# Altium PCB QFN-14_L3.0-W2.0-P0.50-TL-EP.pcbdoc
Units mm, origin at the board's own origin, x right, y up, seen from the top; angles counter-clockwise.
Board outline 15.48 x 16.33 mm, 2 copper layers (Top Layer, Bottom Layer), stack 0 mm thick; 1 components, 0 nets, 12 pads, 0 vias.
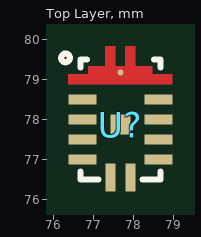
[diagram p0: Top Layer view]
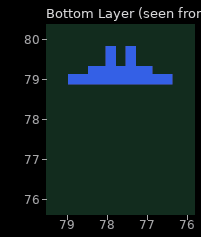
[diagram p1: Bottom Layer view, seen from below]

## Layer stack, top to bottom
Top Layer: signal copper (thickness not stored)
Bottom Layer: signal copper (thickness not stored)

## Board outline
85.333,69.85 69.85,69.85 69.85,86.176 85.333,86.176

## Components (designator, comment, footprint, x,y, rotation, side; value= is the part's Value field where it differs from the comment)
U? "" QFN-14_L3.0-W2.0-P0.50-TL-EP 77.683,77.825 r0 top

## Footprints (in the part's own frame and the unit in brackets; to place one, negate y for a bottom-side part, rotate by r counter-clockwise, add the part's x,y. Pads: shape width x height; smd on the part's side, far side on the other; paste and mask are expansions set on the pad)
QFN-14_L3.0-W2.0-P0.50-TL-EP [mm]
  round 0.148 smd: 1(0,1.352)
  rect 0.7x0.25 smd paste+0 mask+0.05: 2(-0.95,0.675) 3(-0.95,0.175) 4(-0.95,-0.325) 5(-0.95,-0.825) 8(0.95,-0.825) 9(0.95,-0.325) 10(0.95,0.175) 11(0.95,0.675)
  rect 0.25x0.7 smd paste+0 mask+0.05: 6(-0.25,-1.275) 7(0.25,-1.275)
  rect 0.5x0.5 smd paste+0 mask+0.05: 15(0,0.05)
  Top Layer region: -0.127,1.5 -0.127,2 -0.377,2 -0.377,1.5 -0.8,1.5 -0.8,1.3 -1.3,1.3 -1.3,1.05 1.3,1.05 1.3,1.3 0.8,1.3 0.8,1.5 0.373,1.5 0.373,2 0.123,2 0.123,1.5
  Bottom Layer region: -0.127,1.5 -0.127,2 -0.377,2 -0.377,1.5 -0.8,1.5 -0.8,1.3 -1.3,1.3 -1.3,1.05 1.3,1.05 1.3,1.3 0.8,1.3 0.8,1.5 0.373,1.5 0.373,2 0.123,2 0.123,1.5
  Multi-Layer region: -0.127,1.5 -0.127,2 -0.377,2 -0.377,1.5 -0.8,1.5 -0.8,1.3 -1.3,1.3 -1.3,1.05 1.3,1.05 1.3,1.3 0.8,1.3 0.8,1.5 0.373,1.5 0.373,2 0.123,2 0.123,1.5
  silkscreen extent -1.48,-1.32 0.99,1.82

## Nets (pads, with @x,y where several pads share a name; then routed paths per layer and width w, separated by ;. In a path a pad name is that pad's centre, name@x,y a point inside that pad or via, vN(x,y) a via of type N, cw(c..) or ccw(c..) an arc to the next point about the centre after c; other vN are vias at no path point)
pads on no net: U?.1 U?.2 U?.3 U?.4 U?.5 U?.6 U?.7 U?.8 U?.9 U?.10 U?.11 U?.15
